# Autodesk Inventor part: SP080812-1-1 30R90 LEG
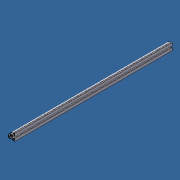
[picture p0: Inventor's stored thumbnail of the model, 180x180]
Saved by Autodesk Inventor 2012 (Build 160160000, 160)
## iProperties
Created: 2012-08
Part Number: SP080812-1-1 30R90 LEG
Material: Aluminum-6061
Document SubType Name: Modeling
Designer: Administrator
Stock Number: 30 R 90 PROFILE
Density: 2.71 g/cm^3
Author: Administrator
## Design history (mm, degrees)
sketch "Sketch1"
  geometry: L1 (4.1, -15)-(4.1, -12.5) reference; L2 (15, -15)-(4.1, -15) reference; L3 (15, -4.1)-(15, -15) reference; L4 (12.5, -4.1)-(15, -4.1) reference; L5 (12.5, -6.8)-(12.5, -4.1) reference; L6 (7.861, -6.8)-(12.5, -6.8) reference; L7 (5.002, -3.941)-(7.861, -6.8) reference; L8 (5.002, 3.941)-(5.002, -3.941) reference; L9 (7.861, 6.8)-(5.002, 3.941) reference; L10 (12.5, 6.8)-(7.861, 6.8) reference; L11 (12.5, 4.1)-(12.5, 6.8) reference; L12 (15, 4.1)-(12.5, 4.1) reference; L13 (15, 15)-(15, 4.1) reference; L14 (-4.1, -15)-(-15, -15) reference; L15 (-4.1, -12.5)-(-4.1, -15) reference; L16 (-6.8, -12.5)-(-4.1, -12.5) reference; L17 (-6.8, -7.861)-(-6.8, -12.5) reference; L18 (-3.941, -5.002)-(-6.8, -7.861) reference; L19 (3.941, -5.002)-(-3.941, -5.002) reference; L20 (6.8, -7.861)-(3.941, -5.002) reference; L21 (6.8, -12.5)-(6.8, -7.861) reference; L22 (4.1, -12.5)-(6.8, -12.5) reference; L23 (13.5, -7.8)-(9.3, -7.8) reference; L24 (14, -12.5)-(14, -8.3) reference; L25 (8.3, -14)-(12.5, -14) reference; L26 (7.8, -9.3)-(7.8, -13.5) reference; L27 (-9.3, -7.8)-(-13.159, -7.8) reference; L28 (-7.8, -13.5)-(-7.8, -9.3) reference; L29 (-12.5, -14)-(-8.3, -14) reference; L30 (14, 8.3)-(14, 12.5) reference; L31 (9.3, 7.8)-(13.5, 7.8) reference; L32 (7.8, 13.159)-(7.8, 9.3) reference; L33 (3.5, -2.086)-(3.419, -2.005) reference; L34 (3.5, -3)-(3.5, -2.086) reference; L35 (2.086, -3.5)-(3, -3.5) reference; L36 (2.005, -3.419)-(2.086, -3.5) reference; L37 (-2.086, -3.5)-(-2.005, -3.419) reference; L38 (-3, -3.5)-(-2.086, -3.5) reference; L39 (-3.5, -2.086)-(-3.5, -3) reference; L40 (-3.419, -2.005)-(-3.5, -2.086) reference; L41 (-3.5, 2.086)-(-3.419, 2.005) reference; L42 (-3.5, 3)-(-3.5, 2.086) reference; L43 (-2.086, 3.5)-(-3, 3.5) reference; L44 (-2.005, 3.419)-(-2.086, 3.5) reference; L45 (2.086, 3.5)-(2.005, 3.419) reference; L46 (3, 3.5)-(2.086, 3.5) reference; L47 (3.5, 2.086)-(3.5, 3) reference; L48 (3.419, 2.005)-(3.5, 2.086) reference; L49 (3.941, 5.002)-(6.8, 7.861) reference; L50 (-3.941, 5.002)-(3.941, 5.002) reference; L51 (-5.333, 6.394)-(-3.941, 5.002) reference; L52 (6.8, 7.861)-(6.8, 12.75) reference; L53 (-5.002, 3.941)-(-6.394, 5.333) reference; L54 (-5.002, -3.941)-(-5.002, 3.941) reference; L55 (-7.861, -6.8)-(-5.002, -3.941) reference; L56 (-12.75, -6.8)-(-7.861, -6.8) reference; L57 (-15, -15)-(-15, -12.5) reference; L58 (15, 15)-(12.5, 15) reference; A1 r 27.5 centre (12.5, -12.5) between (12.5, 15) and (-15, -12.5) reference; A2 r 0.5 centre (13.5, -8.3) between (14, -8.3) and (13.5, -7.8) reference; A3 r 1.5 centre (12.5, -12.5) between (12.5, -14) and (14, -12.5) reference; A4 r 0.5 centre (8.3, -13.5) between (7.8, -13.5) and (8.3, -14) reference; A5 r 1.5 centre (9.3, -9.3) between (9.3, -7.8) and (7.8, -9.3) reference; A6 r 1.5 centre (-9.3, -9.3) between (-7.8, -9.3) and (-9.3, -7.8) reference; A7 r 0.5 centre (-8.3, -13.5) between (-8.3, -14) and (-7.8, -13.5) reference; A8 r 1.5 centre (-12.5, -12.5) between (-14, -12.5) and (-12.5, -14) reference; A9 r 26.5 centre (12.5, -12.5) between (-13.652, -8.219) and (-14, -12.5) reference; A10 r 0.5 centre (-13.159, -8.3) between (-13.159, -7.8) and (-13.652, -8.219) reference; A11 r 1.5 centre (12.5, 12.5) between (14, 12.5) and (12.5, 14) reference; A12 r 0.5 centre (13.5, 8.3) between (13.5, 7.8) and (14, 8.3) reference; A13 r 1.5 centre (9.3, 9.3) between (7.8, 9.3) and (9.3, 7.8) reference; A14 r 0.5 centre (8.3, 13.159) between (8.219, 13.652) and (7.8, 13.159) reference; A15 r 26.5 centre (12.5, -12.5) between (12.5, 14) and (8.219, 13.652) reference; A16 r 0.5 centre (3, -3) between (3, -3.5) and (3.5, -3) reference; A17 r 0.3 centre (1.793, -3.631) between (2.005, -3.419) and (1.66, -3.362) reference; A18 r 3.75 centre (0, 0) between (-1.66, -3.362) and (1.66, -3.362) reference; A19 r 0.3 centre (-1.793, -3.631) between (-1.66, -3.362) and (-2.005, -3.419) reference; A20 r 0.5 centre (-3, -3) between (-3.5, -3) and (-3, -3.5) reference; A21 r 0.3 centre (-3.631, -1.793) between (-3.419, -2.005) and (-3.362, -1.66) reference; A22 r 3.75 centre (0, 0) between (-3.362, 1.66) and (-3.362, -1.66) reference; A23 r 0.3 centre (-3.631, 1.793) between (-3.362, 1.66) and (-3.419, 2.005) reference; A24 r 0.5 centre (-3, 3) between (-3, 3.5) and (-3.5, 3) reference; A25 r 0.3 centre (-1.793, 3.631) between (-2.005, 3.419) and (-1.66, 3.362) reference; A26 r 3.75 centre (0, 0) between (1.66, 3.362) and (-1.66, 3.362) reference; A27 r 0.3 centre (1.793, 3.631) between (1.66, 3.362) and (2.005, 3.419) reference; A28 r 0.5 centre (3, 3) between (3.5, 3) and (3, 3.5) reference; A29 r 0.3 centre (3.631, 1.793) between (3.419, 2.005) and (3.362, 1.66) reference; A30 r 3.75 centre (0, 0) between (3.362, -1.66) and (3.362, 1.66) reference; A31 r 0.3 centre (3.631, -1.793) between (3.362, -1.66) and (3.419, -2.005) reference; A32 r 0.5 centre (-4.98, 6.747) between (-5.316, 7.118) and (-5.333, 6.394) reference; A33 r 26.5 centre (12.5, -12.5) between (6.181, 13.236) and (-5.316, 7.118) reference; A34 r 0.5 centre (6.3, 12.75) between (6.8, 12.75) and (6.181, 13.236) reference; A35 r 0.5 centre (-12.75, -6.3) between (-13.236, -6.181) and (-12.75, -6.8) reference; A36 r 26.5 centre (12.5, -12.5) between (-7.118, 5.316) and (-13.236, -6.181) reference; A37 r 0.5 centre (-6.747, 4.98) between (-6.394, 5.333) and (-7.118, 5.316) reference; 1 further point
  constraints: 116 end point, 74 point on circle, 37 centre point, 21 horizontal, 21 vertical, 2 perpendicular, 2 tangent, 186 other
extrude "Extrusion1" new body sketch "Sketch1" distance "d0" = 704.85; taper "d1" = 0 deg
body "Solid1"
